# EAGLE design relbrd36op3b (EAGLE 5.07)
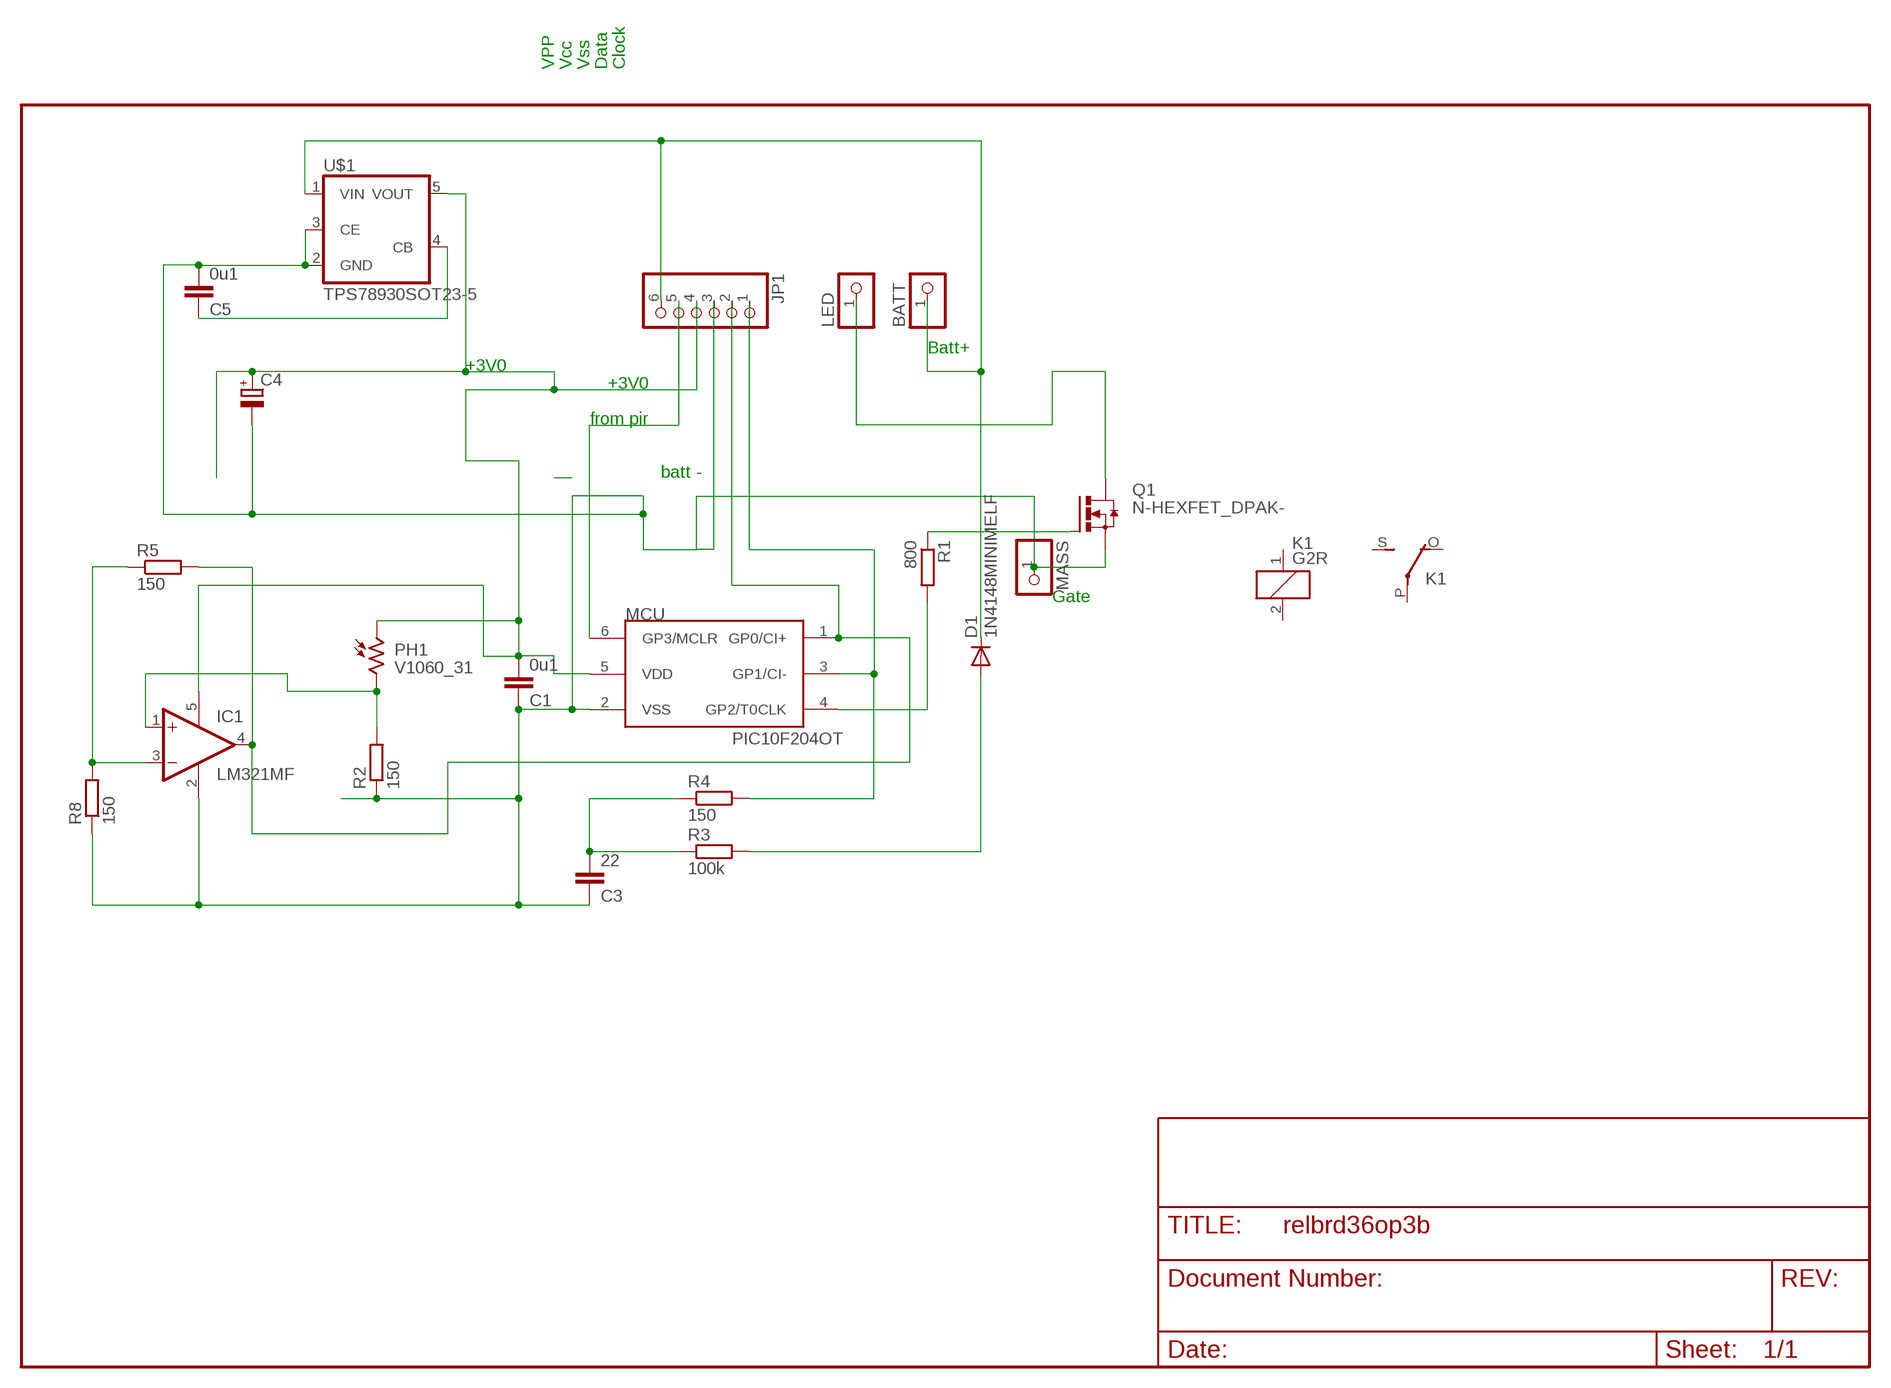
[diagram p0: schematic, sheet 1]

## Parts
BATT  PINHD-1X1  [1X01]
C1  0u1  C-EUC1206  [C1206]
C3  22  C-EUC0805  [C0805]
C4  CPOL-EUSMCA  [SMC_A]
C5  0u1  C-EUC0805  [C0805]
D1  1N4148MINIMELF  [MINIMELF]
IC1  LM321MF  [SOT23-5]
JP1  PINHD-1X6  [1X06BOX]
K1  G2R  [G2R]
LED  PINHD-1X1  [1X01]
MASS  PINHD-1X1  [1X01]
MCU  PIC10F204OT  [SOT23-6]
PH1  V1060_31  [TO-5_V10]
Q1  N-HEXFET_DPAK-  [TO252]
R1  800  R-EU_R0805  [R0805]
R2  150  R-EU_R0805  [R0805]
R3  100k  R-EU_R1206  [R1206]
R4  150  R-EU_R1206  [R1206]
R5  150  R-EU_R1206  [R1206]
R8  150  R-EU_R0805  [R0805]
U$1  TPS78930SOT23-5  [SOT25]

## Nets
BATT+: BATT.1 D1.C JP1.6 U$1.1(VIN)
HOT: LED.1 Q1.3(D)
N$1: Q1.1(G) R1.1
N$4: IC1.4(OUT) JP1.2 MCU.1(GP0/CI+) R5.2
N$5: MCU.4(GP2/T0CLK) R1.2
N$6: IC1.1(+IN) PH1.2 R2.2
N$7: C3.2 R3.1 R4.1
N$8: JP1.1 MCU.3(GP1/CI-) R4.2
N$10: IC1.3(-IN) R5.1 R8.2
N$11: C5.1 U$1.4(CB)
PIR: JP1.5 MCU.6(GP3/MCLR)
V3: C1.2 C4.+ IC1.5(V+) JP1.4 MCU.5(VDD) PH1.1 U$1.5(VOUT)
V+: D1.A R3.2
VSS: C1.1 C3.1 C4.- C5.2 IC1.2(V-) JP1.3 MASS.1 MCU.2(VSS) Q1.2(S) R2.1 R8.1 U$1.2(GND) U$1.3(CE)
Unconnected: K1.1 K1.2 K1.O(2:O) K1.P(2:P) K1.S(2:S)

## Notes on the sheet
- VPP | Vcc | Vss | Data | Clock
- Batt+
- +3V0
- +3V0
- from pir
- batt -
- Gate

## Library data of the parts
BATT LED MASS = pinhead:PINHD-1X1: PIN HEADER
C1 C3 C5 = rcl:C-EU: CAPACITOR, European symbol
C4 = rcl(2):CPOL-EU: POLARIZED CAPACITOR, European symbol
D1 = diode-1:1N4148: DIODE
IC1 = linear:LM321?*: Low Power Single Op Amp Source: http://cache.national.com/ds/LM/LM321.pdf
JP1 = pinhead:PINHD-1X6: PIN HEADER
K1 = relay:G2R: RELAY 1 x switch, Omron
MCU = microchip-3:PIC10F2*: uPC nW 0,25/0,5k Program Flash memory Comparator
PH1 = photo-elements:?1060*: Sensor Street Light control
Q1 = transistor-power:N-HEXFET_?-*: HEXFET® Power MOSFET
R1-R5 R8 = rcl:R-EU_: RESISTOR, European symbol
U$1 = v-reg:TPS78930

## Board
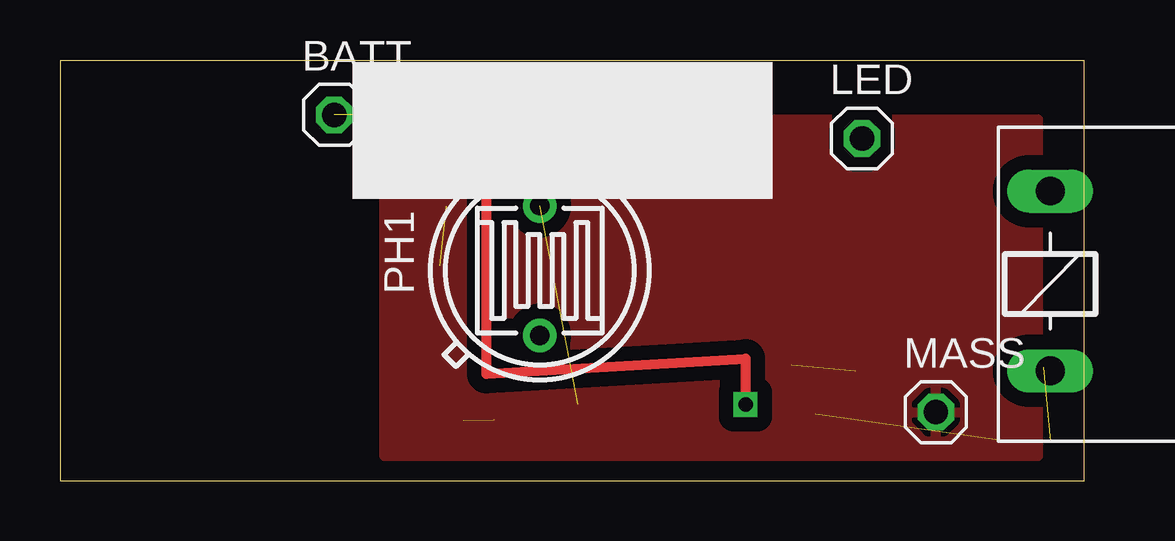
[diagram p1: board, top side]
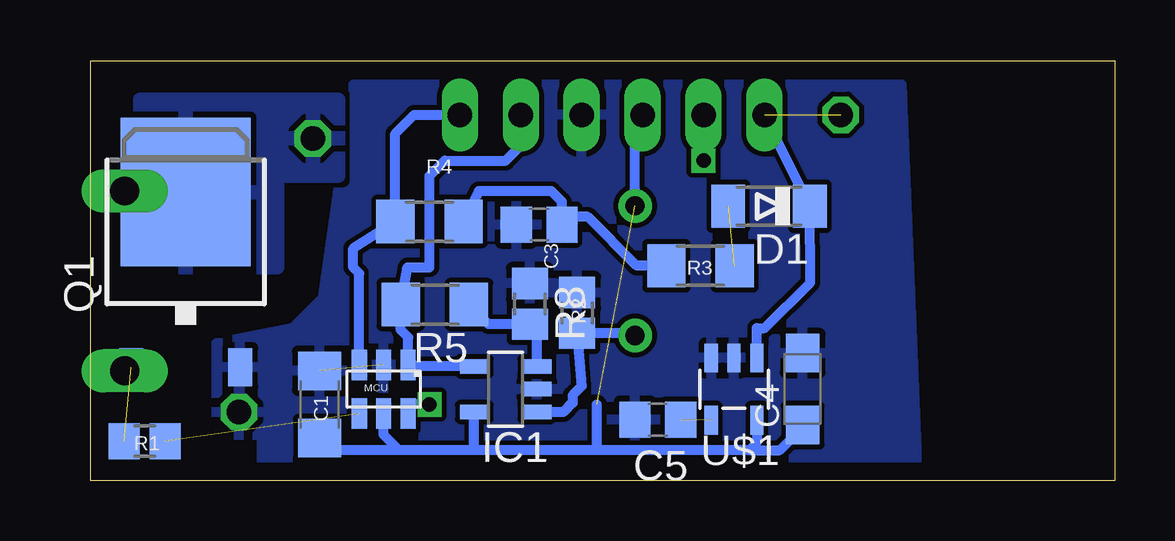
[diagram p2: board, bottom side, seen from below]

Size 42.7 x 17.5 mm. Coordinates in mm from the lower left corner, seen from the top.
Outline: 0,0 42.7,0 42.7,17.5 0,17.5 0,0
Copper layers (1*16): Top 0.035mm / dielectric 1.5mm / Bottom 0.035mm
Design rules "default *": minimum track width 10mil, minimum drill 24mil, track to track 8mil, track to pad 8mil, pad to pad 8mil, via to via 8mil, smd to smd 8mil, copper to edge 30mil, drill to drill 8mil, minimum pad ring 10mil, minimum via ring 8mil, stop-mask expansion 4mil, vias tented up to drill 0mil, thermal gap 10mil

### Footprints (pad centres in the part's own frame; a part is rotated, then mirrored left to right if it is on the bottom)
1X01 = drill 1.016 octagon: 1 0,0
C1206 = smd 1.6 x 1.8: 1 -1.4,0; 2 1.4,0
C0805 = smd 1.3 x 1.5: 1 -0.95,0; 2 0.95,0
SMC_A = smd 1.6 x 1.4: + -1.5,0; - 1.5,0
MINIMELF = smd 1.4 x 1.8: A 1.7,0; C -1.7,0
SOT23-5 = smd 0.6 x 1.2: 1 -0.95,-1.306; 2 0,-1.306; 3 0.95,-1.306; 4 0.95,1.306; 5 -0.95,1.306
1X06BOX = drill 1.016 long: 1 -6.35,0; 2 -3.81,0; 3 -1.27,0; 4 1.27,0; 5 3.81,0; 6 6.35,0
G2R = drill 1.2 pad 1.778 long: 1 -2.54,-3.683; 2 -2.54,3.81; O 13.97,-3.683; P 17.45,3.81; S 20.955,-3.683
SOT23-6 = smd 0.635 x 1.27: 1 -1.016,-1.016; 2 0,-1.016; 3 1.016,-1.016; 4 1.016,1.016; 5 0,1.016; 6 -1.016,1.016
TO-5_V10 = drill 0.8 pad 1.4 round: 1 -2.7,0; 2 2.7,0
TO252 = smd 1 x 1.6: 1 -2.28,-3.53; 2 2.28,-3.53 | smd 5.4 x 6.2: 3 0,3.77
R0805 = smd 1.3 x 1.5: 1 -0.85,0; 2 0.85,0
R1206 = smd 1.6 x 1.803: 1 -1.422,0; 2 1.422,0
SOT25 = smd 0.55 x 1.2: 1 -0.95,-1.3; 2 0,-1.3; 3 0.95,-1.3; 4 0.95,1.3; 5 -0.95,1.3

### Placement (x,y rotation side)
BATT  11.43,15.24 0 top
C1  33.15,3.17 270 bottom
C3  24,10.67 0 bottom
C4  13.02,3.81 90 bottom
C5  19.05,2.54 180 bottom
D1  14.41,11.43 180 bottom
IC1  25.4,3.81 90 bottom
JP1  20.95,15.24 180 top
K1  43.81,8.26 0 top
LED  33.43,14.26 0 top
MASS  36.51,2.86 0 top
MCU  30.48,3.81 180 bottom
PH1  20,8.75 270 top
Q1  38.73,8.26 0 bottom
R1  40.44,1.64 0 bottom
R2  22.42,6.99 270 bottom
R3  17.27,8.95 0 bottom
R4  28.57,10.79 180 bottom
R5  28.35,7.33 180 bottom
R8  24.38,7.37 270 bottom
U$1  15.88,3.81 180 bottom

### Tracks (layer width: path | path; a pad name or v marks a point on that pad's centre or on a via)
BATT+  (1 unrouted)
  Bottom 0.406: JP1.6 14.62,15.24 D1.C 12.7,8.26 14.61,6.35 14.93,6.35 U$1.1
HOT
  pour Bottom (isolate 0.406): 32.38,15.88 32.38,12.7 34.92,12.7 34.92,8.89 40.64,8.89 40.64,15.88
N$1  (1 unrouted)
N$4
  Bottom 0.406: JP1.2 24.77,13.97 25.4,13.34 27.94,13.34 28.57,12.7 28.57,8.89 29.49,8.89 R5.2 29.77,6.28 29.46,5.97 MCU.1 29.4,4.76 IC1.4
N$5  (1 unrouted)
N$6
  Bottom 0.406: IC1.1 22.99,2.86 22.61,3.24 22.61,3.56 22.23,3.94 R2.2 20.09,6.13 PH1.2
N$7
  Bottom 0.406: R3.1 19.94,8.95 21.97,10.99 22.73,10.99 C3.2 23.05,11.62 23.5,12.06 26.52,12.06 R4.1
N$8
  Bottom 0.406: MCU.3 31.5,8.64 31.75,8.89 31.75,9.68 R4.2 30,14.45 29.21,15.24 JP1.1
N$10
  Bottom 0.406: IC1.3 24.09,5.91 R8.2 26.11,6.52 R5.1
N$11  (1 unrouted)
PIR  (via drill 0.6)
  Top 0.406: v17.14,13.34 17.78,13.34 17.78,4.45 28.57,5.08 v28.57,3.17
  Bottom 0.406: v17.14,13.34 JP1.5 | v28.57,3.17 29.46,3.17 MCU.6
V3  (1 unrouted)
  Bottom 0.406: C4.+ 13.02,2.22 13.97,1.27 15.24,1.27 | 15.24,1.27 21.59,1.27 | 21.59,1.27 26.67,1.27 | 26.67,1.27 29.84,1.27 | 29.84,1.27 30.48,1.91 MCU.5 | U$1.5 14.93,1.58 15.24,1.27 | IC1.5 26.71,1.31 26.67,1.27 | 21.59,1.27 21.59,3.17 | PH1.1 20,14.93 JP1.4 | C1.2 32.88,1.77 32.38,1.27 29.84,1.27
V+  (1 unrouted)
VSS  (1 unrouted)
  pour Top (isolate 0.61): 13.78,15.05 40.77,15.05 40.77,1.02 13.53,1.02 13.53,14.35
  pour Bottom (rank 2): 8.89,16.51 31.75,16.51 33.02,7.62 34.29,6.35 37.47,5.71 37.47,1.91 35.56,1.91 35.56,0.64 8.26,0 8.26,1.27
